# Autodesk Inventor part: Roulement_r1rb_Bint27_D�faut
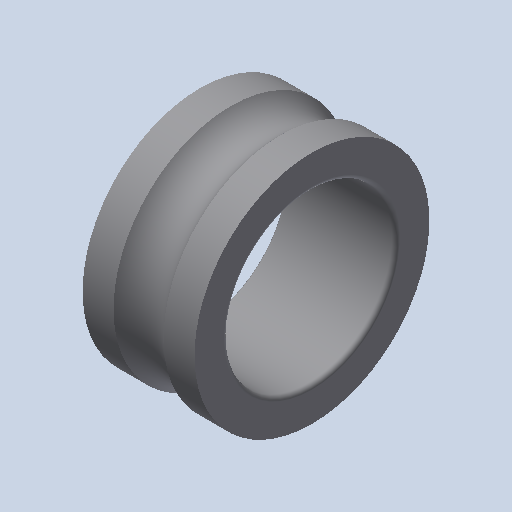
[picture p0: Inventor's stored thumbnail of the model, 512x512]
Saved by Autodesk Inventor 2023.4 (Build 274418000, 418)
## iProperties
Created: 2011-01
Part Number: Roulement_r1rb_Bint27_D�faut
Document SubType Name: Modeling
Designer: eric
Density: 1 g/cm^3
Mass: 0.766536 g
Surface Area: 9.42224 cm^2
Volume: 0.766536 cm^3
Material: Générique
Appearance: Par défaut
Author: eric
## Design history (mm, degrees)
feature "Base1"
node "Corps solides"
node "Corps surfaciques"
node "Solide1"
